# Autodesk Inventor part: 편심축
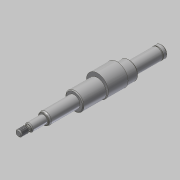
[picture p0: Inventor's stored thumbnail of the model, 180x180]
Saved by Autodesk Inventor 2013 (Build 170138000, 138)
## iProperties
Created: 2015-09
Part Number: 편심축
Material: 강철, 연강
Document SubType Name: Modeling
Designer: mduedu
Density: 1 g/cm^3
Author: mduedu
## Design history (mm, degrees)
sketch "스케치1"
  geometry: L1 (-91, 0)-(91, 0); L2 (-91, 0)-(-91, 7.5); L3 (-91, 7.5)-(-49.85, 7.5); L4 (-49.85, 7.5)-(-49.85, 11.5); L5 (-49.85, 11.5)-(20.15, 11.5); L6 (20.15, 11.5)-(20.15, 7.5); L7 (20.15, 7.5)-(59.15, 7.5); L8 (59.15, 7.5)-(59.15, 5); L9 (59.15, 5)-(78.15, 5); L10 (78.15, 5)-(78.15, 3); L11 (78.15, 3)-(80.15, 3); L12 (81.882, 4)-(91, 4); L13 (91, 4)-(91, 0); L14 (80.15, 3)-(81.882, 4); 2 further points
  constraints: 28 end point, 9 parallel, 2 perpendicular, 1 coincident, 1 collinear, 1 horizontal, 1 midpoint
  dimensions: "d0" = 41.15 distance of L2.end L3.end; "d2" = 70 distance of L4.end L5.end; "d3" = 39 distance of L6.end L7.end; "d4" = 182 distance of L1.start L1.end; "d5" = 19 distance of L8.end L9.end; "d7" = 8 diameter of L12 L1; "d8" = 6 diameter of L11 L1; "d9" = 10 diameter of L9 L1; "d10" = 15 diameter of L7 L1; "d11" = 23 diameter of L5 L1; "d12" = 15 diameter of L3 L1; "d40" = 30 deg angle of L14 L12; "d41" = 2 distance of L10.end L11.end; "d42" = 3.73205 horizontal distance of L12.start L10.end (derived)
revolve "회전1" sketch "스케치1" stored, may be unused: angle "d13" = 90 deg
fillet "모깎기1" dims "d43" = 0.6
sketch "스케치2"
  geometry: L1 (-91, 7.5)-(-49.85, 7.5) reference; L2 (-91, -7.5)-(-91, 7.5) reference; L3 (91, -4)-(91, 4) reference; L4 (-91, 0)-(91, 0); L5 (-86, 7.5)-(-84.85, 7.5); L6 (-84.85, 7.5)-(-84.85, 7.15); L7 (-84.85, 7.15)-(-86, 7.15); L8 (-86, 7.15)-(-86, 7.5); 1 further point
  constraints: 10 end point, 2 midpoint, 2 parallel, 1 horizontal, 1 perpendicular, 1 point on line
  dimensions: "d14" = 5 distance between parallel lines of L8 L2; "d15" = 14.3 diameter of L7 L4; "d16" = 1.15 distance of L6.end L7.end
revolve "회전2" sketch "스케치2" stored, may be unused: angle "d17" = 90 deg
node "작업 평면1"
sketch "스케치3"
  geometry: C1 r 11.5 at (0, 0) reference; C2 r 14 at (0, 2.5); 1 further point
  constraints: 1 centre point, 1 tangent, 1 vertical alignment
  dimensions: "d19" = 28 diameter of C2
extrude "돌출1" join sketch "스케치3" distance "d21" = 25; taper "d22" = 0 deg
node "작업 평면2"
sketch "스케치4"
  geometry: L1 (9.5, 7.5)-(9.5, -7.5) reference; L2 (-9.5, 5)-(-9.5, -5) reference; L3 (9.5, 0)-(-9.5, 0); L4 (-5, -1.5)-(4, -1.5); L5 (4, 1.5)-(-5, 1.5); A1 r 1.5 centre (4, 0) between (4, -1.5) and (4, 1.5); A2 r 1.5 centre (-5, 0) between (-5, 1.5) and (-5, -1.5); 1 further point
  constraints: 6 end point, 4 point on circle, 4 tangent, 2 centre point, 2 midpoint, 2 parallel, 1 point on line
  dimensions: "d23" = 3 distance between parallel lines of L5 L4; "d25" = 12 dimension on A2 A1; "d26" = 3 distance edge to line of A2 L2
extrude "돌출2" cut sketch "스케치4" distance "d27" = 1.8; taper "d28" = 0 deg
chamfer "모따기1" distance "d29" = 1; stored, may be unused: second distance "d30" = 2, angle "d31" = 45 deg
sketch "스케치5"
  geometry: L1 (80.289, 3.08)-(81.882, 4) reference; L2 (81.882, 4)-(91, 4) reference; L3 (91, 4)-(91, -4) reference; L4 (91, -4)-(81.882, -4) reference; L5 (81.882, -4)-(80.289, -3.08) reference; L6 (79.989, -3)-(78.75, -3) reference; L7 (78.15, -3.6)-(78.15, -5) reference; L8 (78.15, -5)-(75.15, -5) reference; L9 (75.15, -5)-(75.15, -3.2) reference; L10 (75.15, -3.2)-(63.15, -3.2) reference; L11 (63.15, -3.2)-(63.15, -5) reference; L12 (63.15, -5)-(59.15, -5) reference; L13 (59.15, -5)-(59.15, -7.5) reference; L14 (59.15, -7.5)-(20.15, -7.5) reference; L15 (20.15, -7.5)-(20.15, -10.5) reference; L16 (20.15, -10.5)-(19.15, -11.5) reference; L17 (19.15, -11.5)-(-9.35, -11.5) reference; L18 (-9.35, -11.5)-(-34.35, -11.5) reference; L19 (-34.35, -11.5)-(-48.85, -11.5) reference; L20 (-48.85, -11.5)-(-49.85, -10.5) reference; L21 (-49.85, -10.5)-(-49.85, -7.5) reference; L22 (-49.85, -7.5)-(-84.85, -7.5) reference; L23 (-84.85, -7.5)-(-84.85, -7.15) reference; L24 (-84.85, -7.15)-(-86, -7.15) reference; L25 (-86, -7.15)-(-86, -7.5) reference; L26 (-86, -7.5)-(-90, -7.5) reference; L27 (-90, -7.5)-(-91, -6.5) reference; L28 (-91, -6.5)-(-91, 6.5) reference; L29 (-91, 6.5)-(-90, 7.5) reference; L30 (-90, 7.5)-(-86, 7.5) reference; L31 (-86, 7.5)-(-86, 7.15) reference; L32 (-86, 7.15)-(-84.85, 7.15) reference; L33 (-84.85, 7.15)-(-84.85, 7.5) reference; L34 (-84.85, 7.5)-(-49.85, 7.5) reference; L35 (-49.85, 7.5)-(-49.85, 10.5) reference; L36 (-49.85, 10.5)-(-48.85, 11.5) reference; L37 (-48.85, 11.5)-(-34.35, 11.5) reference; L38 (-34.35, 11.5)-(-34.35, 16.5) reference; L39 (-34.35, 16.5)-(-9.35, 16.5) reference; L40 (-9.35, 16.5)-(-9.35, 11.5) reference; L41 (-9.35, 11.5)-(19.15, 11.5) reference; L42 (19.15, 11.5)-(20.15, 10.5) reference; L43 (20.15, 10.5)-(20.15, 7.5) reference; L44 (20.15, 7.5)-(59.15, 7.5) reference; L45 (59.15, 7.5)-(59.15, 5) reference; L46 (59.15, 5)-(78.15, 5) reference; L47 (78.15, 5)-(78.15, 3.6) reference; L48 (78.75, 3)-(79.989, 3) reference; L49 (0, 0)-(91, 0); L50 (59.15, -6.55)-(57.505, -7.5); L51 (57.505, -7.5)-(59.15, -7.5); L52 (59.15, -7.5)-(59.15, -6.55); A1 r 0.6 centre (79.989, 3.6) between (79.989, 3) and (80.289, 3.08) reference; A2 r 0.6 centre (79.989, -3.6) between (80.289, -3.08) and (79.989, -3) reference; A3 r 0.6 centre (78.75, -3.6) between (78.75, -3) and (78.15, -3.6) reference; A4 r 0.6 centre (78.75, 3.6) between (78.15, 3.6) and (78.75, 3) reference
  constraints: 8 end point, 2 point on line, 1 midpoint, 1 parallel, 1 perpendicular
  dimensions: "d44" = 30 deg angle of L50 L51; "d45" = 13.1 diameter of L50.start L49
revolve "회전3" sketch "스케치5" stored, may be unused: angle "d46" = 90 deg
fillet "모깎기2" dims "d47" = 4, "d48" = 0.5
feature "스레드1" dims "d32" = 10, "d33" = 0
chamfer "모따기2" distance "d34" = 1; stored, may be unused: second distance "d35" = 2, angle "d36" = 45 deg
chamfer "모따기3" distance "d37" = 1; stored, may be unused: second distance "d38" = 2, angle "d39" = 45 deg
node "솔리드1"
node "절단 모서리 투영1"
other parameters: "d18" = -29.5
